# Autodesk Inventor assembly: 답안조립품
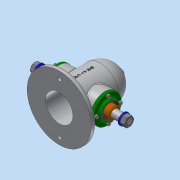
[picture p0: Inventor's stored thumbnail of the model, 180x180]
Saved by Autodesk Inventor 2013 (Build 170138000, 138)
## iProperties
Created: 2019-11
Part Number: 답안조립품
Document SubType Name: Assembly
Designer: Administrator
Author: Administrator
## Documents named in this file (14)
- C:\Users\Administrator\Desktop\491104V1009\답안조립품.iam
- C:\Users\Administrator\Desktop\491104V1009\1-본체.ipt
- C:\Users\Administrator\Desktop\491104V1009\커버.ipt
- C:\Users\Administrator\Desktop\491104V1009\베어링 6203.ipt
- C:\Users\Administrator\Desktop\491104V1009\오일 실 26 38 8.ipt
- C:\Users\Administrator\Desktop\491104V1009\축.ipt
- C:\Users\Administrator\Desktop\491104V1009\키 5x5x12.ipt
- C:\Users\Administrator\Desktop\491104V1009\부시.ipt
- C:\Users\Administrator\Desktop\491104V1009\V-벨트풀리.ipt
- V-벨트풀리.ipt
- C:\Users\Administrator\Desktop\491104V1009\스퍼기어.ipt
- C:\Users\Administrator\Desktop\491104V1009\와셔 12x24.ipt
- C:\Users\Administrator\Desktop\491104V1009\너트 M12x1.25.ipt
- C:\Users\Administrator\Desktop\491104V1009\볼트 M4.ipt
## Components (2 placed, 2 different names)
1. 1-본체:1 — 각도:4, 각도:5, 각도:6, 각도:7
2. V-벨트풀리:1 — 각도:2
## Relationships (5: Angle 5)
- 각도:2 [Angle]: V-벨트풀리:1
- 각도:4 [Angle]: 1-본체:1
- 각도:5 [Angle]: 1-본체:1
- 각도:6 [Angle]: 1-본체:1
- 각도:7 [Angle]: 1-본체:1
